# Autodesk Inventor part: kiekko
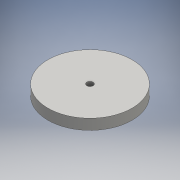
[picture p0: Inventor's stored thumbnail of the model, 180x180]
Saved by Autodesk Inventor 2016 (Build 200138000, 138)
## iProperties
Created: 2016-02
Part Number: kiekko
Material: Generic
Document SubType Name: Modeling
Designer: Juha-Pekka
Density: 1 g/cm^3
Appearance: Default
Author: Juha-Pekka
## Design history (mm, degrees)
sketch "Sketch1"
  geometry: C1 r 40 at (0, 0); 1 further point
  constraints: 1 centre point, 1 coincident
  dimensions: "d0" = 80 diameter of C1
extrude "Extrusion1" new body sketch "Sketch1" distance "d1" = 10; taper "d2" = 0 deg
sketch "Sketch2"
  geometry: C1 r 7.818 at (0, 0); 1 further point
  constraints: 1 centre point, 1 coincident
hole "Hole1" sketch "Sketch2" at (0, 0) diameter "d3" = 6; stored, may be unused: countersink angle "d7" = 90 deg, drill point angle "d9" = 118 deg; dims "d4" = 6, "d5" = 4, "d6" = 2, "d8" = 8
body "Solid1"
